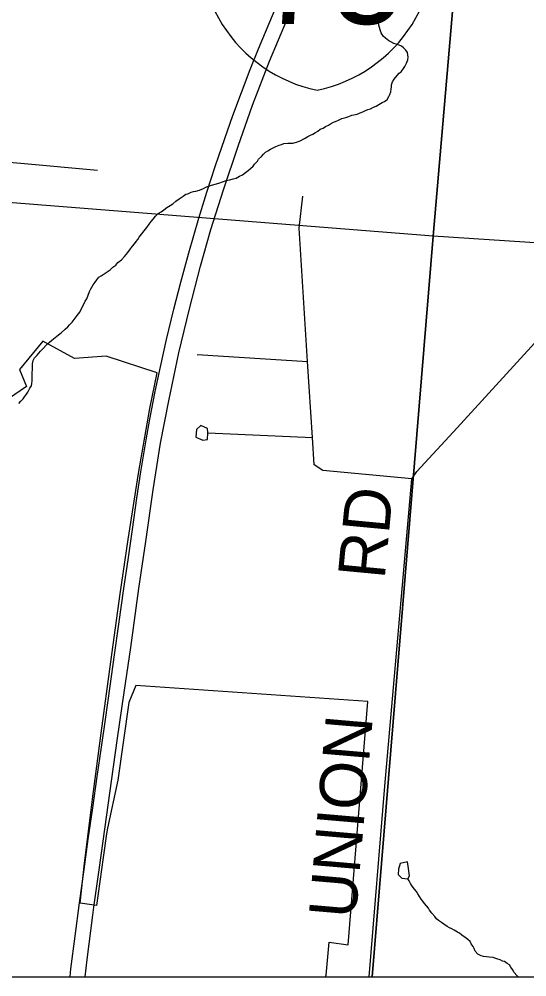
# Model space of a CAD drawing. Extents: x -7.3 to 34, y 0 to 22.
# Drawn here: x 4.796 to 5.41, y 14.1 to 15.258 of the extents above; entities that cross this region are included whole.
import ezdxf

# ---------------------------------------------------------------- set-up
doc = ezdxf.new("R2010")
doc.units = 0
for name, color, linetype in [('GM_X_Corporation', 7, 'Continuous'), ('GM_X_County_Road', 7, 'Continuous'), ('GM_X_County_Road_Text', 7, 'Continuous'), ('GM_X_Interstate_Route', 7, 'Continuous'), ('GM_X_Interstate_Shield', 7, 'Continuous'), ('GM_X_Minor_Lake', 7, 'Continuous'), ('GM_X_Minor_River', 7, 'Continuous'), ('GM_X_Township_Road', 7, 'Continuous'), ('SH_Data', 7, 'Continuous')]:
    doc.layers.add(name, color=color, linetype=linetype)

msp = doc.modelspace()

# ---------------------------------------------------------------- linework, layer by layer
at = {"layer": 'GM_X_Corporation'}
for points in [[(4.3152, 15.5847), (4.2701, 15.1232), (4.2655, 15.0758), (4.2591, 15.0066), (4.246, 14.8644), (4.233, 14.7229), (4.2199, 14.5807), (4.1921, 14.279), (4.1756, 14.1), (8.9, 14.1), (8.9, 19.7858)], [(4.3152, 15.5847), (4.2701, 15.1232), (4.2655, 15.0758), (4.2591, 15.0066), (4.246, 14.8644), (4.233, 14.7229), (4.2199, 14.5807), (4.1921, 14.279), (4.1756, 14.1), (8.3447, 14.1), (8.3604, 14.2653), (8.3676, 14.3403), (8.3685, 14.3492), (8.4214, 14.9056), (8.4562, 15.2161), (8.4601, 15.2687)], [(2.1, 14.1), (5.1665, 14.1), (5.1673, 14.1021), (5.1709, 14.1421), (5.1939, 14.1386), (5.2176, 14.4327), (4.937, 14.4522), (4.9286, 14.4314), (4.9153, 14.3376), (4.9028, 14.2799), (4.9013, 14.2727), (4.8973, 14.2444), (4.8893, 14.1862), (4.8695, 14.189), (4.8747, 14.2375), (4.8843, 14.3146), (4.8951, 14.3945), (4.9068, 14.4807), (4.918, 14.5628), (4.9277, 14.6286), (4.94, 14.7083), (4.9538, 14.7869), (4.9628, 14.8299), (4.901, 14.85), (4.8625, 14.8473), (4.8242, 14.8685), (4.7963, 14.8341), (4.8045, 14.8137), (4.7828, 14.7985)]]:
    msp.add_lwpolyline(points, dxfattribs=at)
for points in [[(4.3675, 16.1154), (5.3843, 16.0117), (5.2968, 14.9953), (4.2681, 15.0765)], [(5.3843, 16.0117), (6.4371, 15.9508), (6.3438, 14.9266), (5.2968, 14.9953)], [(4.176, 14.1), (5.223, 14.1), (5.2968, 14.9953), (4.2681, 15.0765)], [(5.223, 14.1), (6.2678, 14.1), (6.3438, 14.9266), (5.2968, 14.9953)]]:
    msp.add_lwpolyline(points, close=True, dxfattribs=at)
at = {"layer": 'GM_X_County_Road'}
msp.add_lwpolyline([(5.219, 14.1), (5.2383, 14.3304), (5.2709, 14.7021), (5.2768, 14.7107), (5.3257, 14.7637), (5.4619, 14.9128), (5.492, 14.945), (5.517, 14.9838), (5.5831, 15.0835), (5.6007, 15.1153), (5.611, 15.1424), (5.6526, 15.2909), (5.6914, 15.4165), (5.6931, 15.4241), (5.695, 15.4332), (5.6976, 15.4484), (5.6994, 15.4652), (5.7005, 15.479)], dxfattribs=at)
at = {"layer": 'GM_X_Interstate_Route'}
for points in [[(4.8573, 14.1), (4.8584, 14.1097), (4.8633, 14.149), (4.8686, 14.1895), (4.8743, 14.2296), (4.8794, 14.2666), (4.8848, 14.3041), (4.8901, 14.3421), (4.8952, 14.3777), (4.9002, 14.4112), (4.9058, 14.4515), (4.9111, 14.489), (4.9164, 14.5261), (4.9225, 14.5692), (4.9277, 14.6041), (4.9327, 14.6406), (4.9381, 14.6785), (4.9429, 14.7104), (4.9493, 14.7491), (4.954, 14.7742), (4.9604, 14.8075), (4.9666, 14.8371), (4.9741, 14.8704), (4.9828, 14.907), (4.9912, 14.9398), (5.001, 14.9752), (5.0131, 15.0171), (5.0228, 15.0484), (5.0334, 15.0806), (5.0445, 15.1134), (5.0543, 15.1411), (5.0647, 15.1689), (5.0753, 15.1968), (5.0853, 15.2215), (5.1073, 15.2745)], [(4.8861, 14.1843), (4.8924, 14.2292), (4.8998, 14.2813), (4.9075, 14.3367), (4.9149, 14.3883), (4.9226, 14.4437), (4.9307, 14.4981), (4.9407, 14.5692), (4.9488, 14.626), (4.9577, 14.6885), (4.9669, 14.745), (4.9767, 14.7963), (4.9889, 14.8542), (5.0018, 14.9075), (5.0151, 14.959), (5.0278, 15.0034), (5.0428, 15.0513), (5.0606, 15.1041), (5.0782, 15.1536), (5.0986, 15.2068), (5.1202, 15.2584)], [(4.8755, 14.1), (4.8779, 14.1208), (4.8847, 14.1744), (4.8861, 14.1843)]]:
    msp.add_lwpolyline(points, dxfattribs=at)
at = {"layer": 'GM_X_Interstate_Shield'}
for centre, start, end in [((5.1918, 15.3457), 165.8066, 258.463), ((5.1207, 15.3457), 281.537, 14.1934)]:
    msp.add_arc(centre, 0.1776, start, end, dxfattribs=at)
at = {"layer": 'GM_X_Minor_Lake'}
for points in [[(5.2664, 14.2336), (5.2657, 14.2392), (5.2565, 14.2371), (5.2545, 14.2303), (5.2543, 14.2235), (5.2588, 14.2192), (5.266, 14.2183)], [(5.266, 14.2183), (5.2679, 14.222), (5.2664, 14.2336)]]:
    msp.add_lwpolyline(points, dxfattribs=at)
at = {"layer": 'GM_X_Minor_River'}
for points in [[(5.0997, 15.1002), (5.1024, 15.1017), (5.1062, 15.1035), (5.1104, 15.1053), (5.1131, 15.106), (5.1158, 15.1071), (5.1207, 15.1077), (5.1238, 15.1077), (5.1268, 15.1076), (5.1314, 15.1087), (5.1356, 15.1105), (5.141, 15.1134), (5.1448, 15.1156), (5.1482, 15.1174), (5.1509, 15.1185), (5.1544, 15.1207), (5.1571, 15.1222), (5.1598, 15.1244), (5.1636, 15.1258), (5.1663, 15.1277), (5.1698, 15.1295), (5.1724, 15.1309), (5.1759, 15.1328), (5.1786, 15.1338), (5.182, 15.1353), (5.1862, 15.1375), (5.1908, 15.1385), (5.1946, 15.14), (5.1981, 15.1414), (5.2007, 15.1417), (5.2046, 15.1428), (5.2076, 15.1439), (5.2122, 15.1457), (5.2149, 15.1471), (5.2176, 15.1482), (5.2206, 15.1493), (5.2245, 15.1511), (5.2275, 15.1525), (5.231, 15.1544), (5.2348, 15.1566), (5.2379, 15.158), (5.241, 15.1602), (5.243, 15.164), (5.2442, 15.1666), (5.2454, 15.1696), (5.2458, 15.173), (5.2462, 15.1757), (5.2463, 15.1783), (5.2475, 15.1817), (5.2495, 15.1851), (5.253, 15.1896), (5.2553, 15.1922), (5.258, 15.194), (5.2608, 15.1978), (5.2623, 15.2004), (5.2643, 15.2045), (5.2659, 15.2083), (5.2664, 15.2117), (5.2661, 15.2144), (5.2654, 15.2171), (5.2635, 15.2201), (5.2609, 15.2229), (5.2583, 15.2248), (5.2553, 15.226), (5.2519, 15.2272), (5.2489, 15.2281), (5.2455, 15.23), (5.2429, 15.2312), (5.2388, 15.2344), (5.2362, 15.2371), (5.2336, 15.2409), (5.2326, 15.2444), (5.2308, 15.2501), (5.2305, 15.2532), (5.2298, 15.2581)], [(4.8109, 14.817), (4.8114, 14.8204), (4.8115, 14.8242), (4.8116, 14.8276), (4.8116, 14.8303), (4.8117, 14.8337), (4.8117, 14.8364), (4.8118, 14.8409), (4.8127, 14.8451), (4.8143, 14.8481), (4.8174, 14.8514), (4.8217, 14.8563), (4.8252, 14.86), (4.8286, 14.8633), (4.8321, 14.8667), (4.8352, 14.8697), (4.8391, 14.8726), (4.8433, 14.8759), (4.8464, 14.8785), (4.8515, 14.883), (4.8545, 14.8856), (4.8565, 14.8882), (4.86, 14.8912), (4.8635, 14.896), (4.8658, 14.8994), (4.869, 14.9035), (4.871, 14.9076), (4.8729, 14.9106), (4.8757, 14.9166), (4.8777, 14.9196), (4.8793, 14.9238), (4.8809, 14.9283), (4.8821, 14.9309), (4.8837, 14.9336), (4.8852, 14.9362), (4.8876, 14.9396), (4.8899, 14.9426), (4.8923, 14.9455), (4.895, 14.9474), (4.8984, 14.9496), (4.9011, 14.9514), (4.9057, 14.9547), (4.9092, 14.9577), (4.9127, 14.9603), (4.915, 14.9633), (4.9197, 14.9666), (4.9232, 14.9707), (4.9271, 14.9756), (4.9306, 14.98), (4.9329, 14.983), (4.9352, 14.986), (4.9372, 14.9886), (4.9392, 14.9913), (4.9411, 14.9939), (4.9442, 14.998), (4.947, 15.0017), (4.9501, 15.0055), (4.9532, 15.0099), (4.9556, 15.0129), (4.9579, 15.0159), (4.9606, 15.0193), (4.9641, 15.0226), (4.9676, 15.0248), (4.9707, 15.027), (4.9745, 15.03), (4.9784, 15.0322), (4.9818, 15.0344), (4.9853, 15.0374), (4.9892, 15.0403), (4.9942, 15.0436), (4.9972, 15.0458), (4.9999, 15.0465), (5.0037, 15.0484), (5.0068, 15.0491), (5.0095, 15.0498), (5.014, 15.0508), (5.0186, 15.053), (5.0217, 15.0544), (5.0248, 15.0555), (5.0286, 15.0569), (5.0328, 15.058), (5.0374, 15.0594), (5.0416, 15.0608), (5.0462, 15.0623), (5.0507, 15.0633), (5.0545, 15.0644), (5.0584, 15.0654), (5.0622, 15.0676), (5.066, 15.0694), (5.0695, 15.072), (5.0726, 15.0746), (5.0757, 15.0768), (5.0788, 15.0798), (5.0803, 15.0824), (5.0842, 15.0857), (5.0854, 15.0884), (5.0889, 15.0917), (5.0912, 15.0943), (5.0939, 15.0966), (5.0966, 15.0984), (5.0997, 15.1002)], [(4.7953, 14.793), (4.7976, 14.7956), (4.8007, 14.7986), (4.8023, 14.8012), (4.8046, 14.8042), (4.8062, 14.8068), (4.8085, 14.8114), (4.8105, 14.8143), (4.8109, 14.817)], [(5.2693, 14.2129), (5.2674, 14.216), (5.266, 14.2183)], [(5.3993, 14.1), (5.3977, 14.1018), (5.3944, 14.1053), (5.3925, 14.1088), (5.3907, 14.1118), (5.3889, 14.1145), (5.3863, 14.1161), (5.3829, 14.1185), (5.3803, 14.1189), (5.3776, 14.1205), (5.375, 14.1213), (5.3724, 14.1221), (5.369, 14.1233), (5.3644, 14.1238), (5.361, 14.1243), (5.3576, 14.1247), (5.3546, 14.1255), (5.3505, 14.1275), (5.3475, 14.131), (5.3461, 14.1341), (5.345, 14.1368), (5.3424, 14.1399), (5.3413, 14.1429), (5.3387, 14.1453), (5.3354, 14.1476), (5.3312, 14.1504), (5.3286, 14.1527), (5.326, 14.1539), (5.3219, 14.1563), (5.3193, 14.1579), (5.3163, 14.1591), (5.3137, 14.161), (5.3095, 14.1638), (5.3065, 14.1657), (5.3032, 14.1681), (5.3006, 14.17), (5.2987, 14.1731), (5.295, 14.177), (5.2921, 14.1805), (5.291, 14.1832), (5.2884, 14.1859), (5.2862, 14.1886), (5.2843, 14.1913), (5.2821, 14.194), (5.2799, 14.1971), (5.2781, 14.2002), (5.2763, 14.2032), (5.274, 14.2059), (5.2711, 14.2094), (5.2693, 14.2129)]]:
    msp.add_lwpolyline(points, dxfattribs=at)
at = {"layer": 'GM_X_Township_Road'}
msp.add_line((5.0112, 14.8521), (5.1447, 14.8439), dxfattribs=at)
for points in [[(4.7229, 15.0899), (4.7979, 15.0833), (4.8907, 15.075)], [(5.2709, 14.7021), (5.1633, 14.7118), (5.1525, 14.7189), (5.1505, 14.7517), (5.1447, 14.8439), (5.1345, 15.0049), (5.139, 15.0435)], [(5.0241, 14.7579), (5.0235, 14.7629), (5.0156, 14.7665), (5.0104, 14.7617), (5.0096, 14.7522), (5.0181, 14.7487), (5.0237, 14.7496), (5.0241, 14.7577), (5.1505, 14.7517)]]:
    msp.add_lwpolyline(points, dxfattribs=at)
at = {"layer": 'SH_Data'}
msp.add_line((2.1, 14.1), (8.9, 14.1), dxfattribs=at)

# ---------------------------------------------------------------- texts
at = {"layer": 'GM_X_County_Road_Text'}
for s, rotation, p in [('RD', 84.5821, (5.2378, 14.5797)), ('UNION', 85.0941, (5.2027, 14.1693))]:
    msp.add_text(s, height=0.05682, rotation=rotation, dxfattribs=at).set_placement(p)
at = {"layer": 'GM_X_Interstate_Shield'}
msp.add_text('75', height=0.11837, dxfattribs=at).set_placement((5.0856, 15.2517))

doc.saveas('drawing.dxf')
